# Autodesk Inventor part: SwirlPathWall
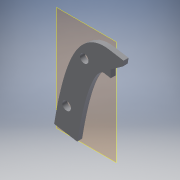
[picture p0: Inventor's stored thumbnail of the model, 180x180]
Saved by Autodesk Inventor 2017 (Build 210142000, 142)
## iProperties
Created: 2017-05
Part Number: SwirlPathWall
Material: Generic
Document SubType Name: Modeling
Designer: 1460374
Density: 1 g/cm^3
Appearance: Default
Author: 1460374
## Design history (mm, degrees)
workplane "Work Plane1"
sketch "Sketch1" dims "d0" = 17.78
  geometry: L1 (17.426, 20.735)-(20.317, 38.278); L2 (-3.526, -34.773)-(-21.069, -31.882); C1 r 3.175 at (1.862, 22.806) reference; C2 r 3.175 at (-11.526, -15.179) reference; 2 further points
  constraints: 4 end point, 1 perpendicular, 4 other
extrude "Extrusion1" new body sketch "Sketch1" distance "d1" = 3.81; taper "d2" = 0 deg
sketch "Sketch2"
  geometry: L1 (0, -17.78)-(0, 0) reference; L2 (3.81, -17.844)-(0, -17.844); L3 (0, -17.844)-(0, 0); L4 (0, 0)-(3.81, 0); L5 (3.81, 0)-(3.81, -17.844); 1 further point
  constraints: 8 end point, 2 parallel, 1 horizontal, 1 perpendicular
extrude "Extrusion2" join sketch "Sketch2" distance "d3" = 11.7475; taper "d4" = 0 deg
sketch "Sketch3"
  geometry: L1 (33.805, 34.028)-(22.142, 25.665) reference; L2 (22.142, 25.665)-(22.142, 19.892); L3 (17.415, 20.672)-(29.006, 18.761) reference; L4 (31.908, 36.368)-(29.006, 18.761) reference; L5 (31.217, 32.172)-(29.006, 18.761); L6 (29.006, 18.761)-(22.142, 19.892); L7 (31.217, 32.172)-(22.142, 25.665); A1 r 6.35 centre (20.5, 19.531) between (22.142, 25.665) and (19.405, 25.786) reference; 1 further point
  constraints: 8 end point, 3 point on line, 2 collinear, 1 perpendicular, 1 vertical
extrude "Extrusion3" cut sketch "Sketch3" distance "d5" = 3.81; taper "d6" = 0 deg
sketch "Sketch4"
  geometry: L1 (22.142, 19.892)-(22.142, 25.665) reference; L2 (22.142, 25.665)-(31.217, 32.172) reference; L3 (31.908, 36.368)-(31.217, 32.172) reference; L4 (20.317, 38.278)-(31.908, 36.368) reference; L5 (-21.069, -31.882)-(-3.526, -34.773) reference; L6 (17.415, 20.672)-(17.426, 20.735) reference; L7 (17.415, 20.672)-(22.142, 19.892) reference; C1 r 3.175 at (1.862, 22.806) reference; C2 r 3.175 at (-11.526, -15.179) reference; C3 r 3.175 at (-11.526, -15.179) reference; C4 r 3.275 at (1.862, 22.806); C5 r 3.275 at (-11.526, -15.179); 1 further point
  constraints: 2 centre point, 2 other
  dimensions: "d7" = 0.1 radial gap between concentric circles of C1 C4; "d8" = 0.1 radial gap between concentric circles of C2 C5
  node "Projected Loop1"
workplane "Work Plane2"
body "Solid1"
node "Reference1"
node "Reference2"
node "Reference3"
node "Reference4"
node "Reference5"
